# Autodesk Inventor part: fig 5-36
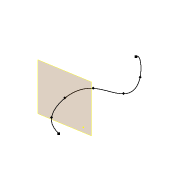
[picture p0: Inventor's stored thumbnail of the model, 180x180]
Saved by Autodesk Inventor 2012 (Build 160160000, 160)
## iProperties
Created: 2010-02
Part Number: fig 5-36
Document SubType Name: Modeling
Designer: CADSoft
Density: 1 g/cm^3
Material: Default
Author: CADSoft
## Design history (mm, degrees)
sketch "Sketch1"
  geometry: 8 further points
  constraints: 8 other
workplane "Work Plane1"
workplane "Work Plane2"
